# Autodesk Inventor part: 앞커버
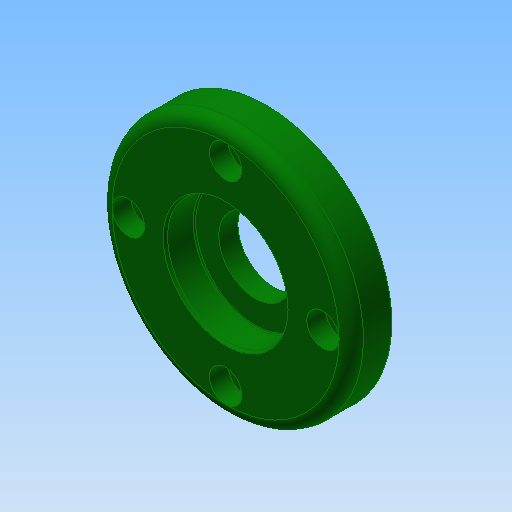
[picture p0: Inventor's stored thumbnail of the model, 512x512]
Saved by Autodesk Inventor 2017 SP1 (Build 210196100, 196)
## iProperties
Created: 2015-09
Part Number: 앞커버
Material: 알루미늄 6061
Document SubType Name: Modeling
Designer: mduedu
Density: 1 g/cm^3
Appearance: 진녹색
Author: mduedu
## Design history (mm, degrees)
sketch "스케치1"
  geometry: L1 (0, 7.5)-(0, -7.5); L2 (0, 7.5)-(31, 7.5); L3 (31, 7.5)-(31, -2.5); L4 (31, -2.5)-(17.5, -2.5); L5 (17.5, -2.5)-(17.5, -7.5); L6 (17.5, -7.5)-(0, -7.5); 2 further points
  constraints: 12 end point, 2 parallel, 2 perpendicular, 1 coincident, 1 horizontal, 1 midpoint, 1 vertical
  dimensions: "d0" = 15 distance of L1.start L1.end; "d1" = 62 diameter of L3 L1; "d2" = 35 diameter of L5 L1; "d3" = 10 distance of L2.end L3.end
revolve "회전1" sketch "스케치1" stored, may be unused: angle "d4" = 90 deg
hole "구멍1" diameter "d7" = 30; stored, may be unused: countersink angle "d11" = 90 deg, drill point angle "d13" = 0 deg; dims "d5" = 10, "d6" = 10, "d8" = 6, "d9" = 4, "d10" = 2, "d12" = 7.3
hole "구멍2" diameter "d16" = 18; stored, may be unused: countersink angle "d20" = 90 deg, drill point angle "d22" = 0 deg; dims "d14" = 10, "d15" = 10, "d17" = 6, "d18" = 4, "d19" = 2, "d21" = 7.3
chamfer "모따기2" distance "d26" = 0.7; stored, may be unused: second distance "d27" = 2, angle "d28" = 30 deg
fillet "모깎기1" dims "d29" = 0.3
sketch "스케치3"
  geometry: C1 r 15.404 at (0, 0) reference; A1 r 24 centre (0, 0) between (0, 24) and (0, -24); 2 further points
  constraints: 4 point on circle, 2 horizontal alignment, 2 vertical alignment, 1 centre point, 1 coincident
  dimensions: "d60" = 48 diameter of A1
hole "구멍3" sketch "스케치3" at (0, 24), (-24, 0), (24, 0), (0, -24) diameter "d36" = 4.5; stored, may be unused: countersink angle "d40" = 90 deg, drill point angle "d42" = 0 deg; dims "d37" = 6, "d38" = 8, "d39" = 4.6, "d41" = 8
chamfer "모따기3" distance "d43" = 1; stored, may be unused: second distance "d44" = 2, angle "d45" = 45 deg
fillet "모깎기2" dims "d46" = 3
hole "구멍4" diameter "d49" = 30; stored, may be unused: countersink angle "d53" = 90 deg, drill point angle "d55" = 0 deg; dims "d50" = 6, "d51" = 4, "d52" = 2, "d54" = 3, "d56" = 10, "d57" = 10
fillet "모깎기3" dims "d58" = 3
node "솔리드1"
sketch "스케치2" dims "d30" = 48
  geometry: 6 further points
  constraints: 2 vertical alignment, 1 coincident, 7 other
  dimensions: "d34" = 360 deg dimension on point (0, 0) point (0, 24) (derived)
